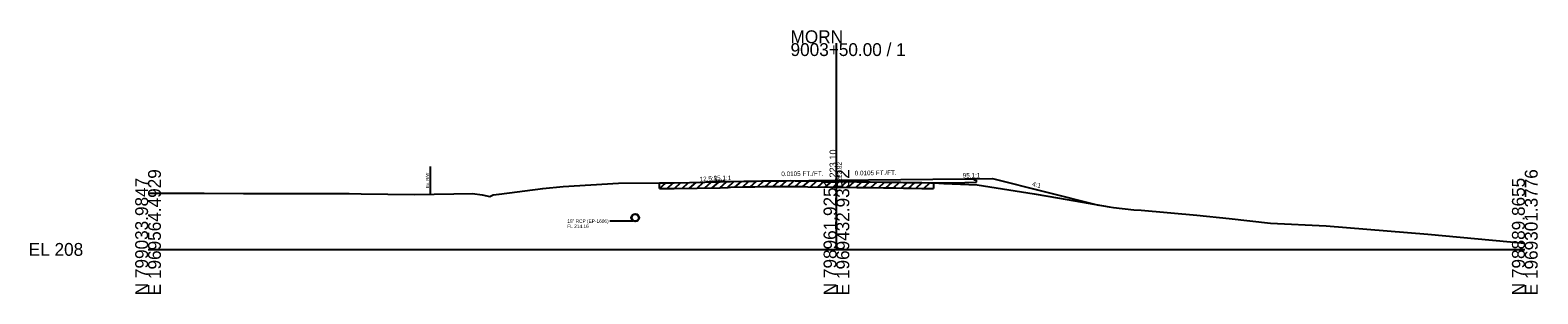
# Model space of a CAD drawing. Extents: x -26 to 2313, y -1511 to 5559.
# Drawn here: x -25.7 to 302.8, y 1490.3 to 1547.8 of the extents above; entities that cross this region are included whole.
import ezdxf

# ---------------------------------------------------------------- set-up
doc = ezdxf.new("R2010")
doc.units = 0
for name, color, linetype in [('RD_GPK_XS_Cell', 7, 'Continuous'), ('RD_XS_Base', 7, 'Continuous'), ('RD_XS_EarthShd', 7, 'Continuous'), ('RD_XS_ExGround', 7, 'Continuous'), ('RD_XS_ExPaveRet', 7, 'Continuous'), ('RD_XS_ExRW', 7, 'Continuous'), ('RD_XS_Misc_Line', 7, 'Continuous'), ('RD_XS_Pave', 7, 'Continuous'), ('RD_XS_PaveOvlay', 7, 'Continuous'), ('RD_XS_PaveShd', 7, 'Continuous'), ('RD_XS_Pipe', 7, 'Continuous'), ('RD_XS_TieSlope', 7, 'Continuous'), ('RD_XS_TX_Elev_EX', 7, 'Continuous'), ('RD_XS_TX_Elev_PR', 7, 'Continuous'), ('RD_XS_TX_Profile', 7, 'Continuous'), ('RD_XS_TX_ShdSlope', 7, 'Continuous'), ('RD_XS_TX_Slope', 7, 'Continuous')]:
    doc.layers.add(name, color=color, linetype=linetype)

msp = doc.modelspace()

# ---------------------------------------------------------------- linework, layer by layer
at = {"layer": 'RD_GPK_XS_Cell'}
for p, q in [((150, 1500), (150, 1544.96)), ((0, 1500), (150, 1500)), ((150, 1500), (300, 1500))]:
    msp.add_line(p, q, dxfattribs=at)
at = {"layer": 'RD_XS_Base'}
for p, q in [((123.72, 1514.68), (123.72, 1514.82)), ((178, 1514.61), (180.5, 1514.64)), ((180, 1515.11), (180, 1515.41)), ((180.5, 1515.12), (180, 1515.11)), ((180.5, 1514.64), (180.5, 1515.12))]:
    msp.add_line(p, q, dxfattribs=at)
at = {"layer": 'RD_XS_EarthShd'}
for p, q in [((123.72, 1514.82), (121.51, 1514.64)), ((180, 1515.41), (184, 1515.45))]:
    msp.add_line(p, q, dxfattribs=at)
at = {"layer": 'RD_XS_ExGround'}
msp.add_lwpolyline([(0, 1512.25), (5.29, 1512.27), (12.21, 1512.25), (20.79, 1512.22), (31.25, 1512.22), (38.81, 1512.2), (43.82, 1512.19), (46.43, 1512.13), (58.04, 1512), (66.62, 1512.1), (70.68, 1512.17), (72.77, 1511.88), (74.46, 1511.55), (75.22, 1511.87), (76.54, 1512.07), (86.05, 1513.31), (90.47, 1513.74), (102.53, 1514.41), (111.43, 1514.53), (114.63, 1514.52), (124.66, 1514.7), (126.44, 1514.78), (126.91, 1514.79), (129.82, 1514.86), (130.15, 1514.86), (130.61, 1514.87), (131.27, 1514.89), (132.24, 1514.9), (133.75, 1514.93), (134.81, 1514.94), (135.64, 1514.96), (136.59, 1514.95), (138.74, 1514.97), (139.14, 1514.97), (140.09, 1514.99), (141, 1514.95), (142.47, 1514.94), (142.83, 1514.94), (143.77, 1514.92), (149.48, 1514.83), (150, 1514.82), (150.46, 1514.81), (154.48, 1514.76), (157.37, 1514.72), (160.29, 1514.68), (162.26, 1514.66), (162.93, 1514.66), (164.58, 1514.62), (165.8, 1514.59), (166.36, 1514.58), (168.58, 1514.55), (170.52, 1514.52), (171.18, 1514.5), (173.43, 1514.39), (180.68, 1514.07), (193.06, 1512.09), (198.58, 1511.17), (209.41, 1509.27), (210.35, 1509.17), (214.79, 1508.66), (216.38, 1508.52), (228.51, 1507.44), (235.61, 1506.74), (244.56, 1505.75), (256.71, 1505.15), (278.85, 1503.32), (300, 1501.36)], dxfattribs=at)
at = {"layer": 'RD_XS_ExPaveRet'}
for p, q in [((111.43, 1513.28), (111.43, 1514.53)), ((111.43, 1513.28), (114.63, 1513.27)), ((114.63, 1513.27), (124.66, 1513.45)), ((124.66, 1513.45), (126.44, 1513.53)), ((126.44, 1513.53), (126.91, 1513.54)), ((126.91, 1513.54), (129.82, 1513.61)), ((129.82, 1513.61), (130.15, 1513.61)), ((130.15, 1513.61), (130.61, 1513.62)), ((130.61, 1513.62), (131.27, 1513.64)), ((131.27, 1513.64), (132.24, 1513.65)), ((132.24, 1513.65), (133.75, 1513.68)), ((133.75, 1513.68), (134.81, 1513.69)), ((134.81, 1513.69), (135.64, 1513.71)), ((135.64, 1513.71), (136.59, 1513.7)), ((136.59, 1513.7), (138.74, 1513.72)), ((138.74, 1513.72), (139.14, 1513.72)), ((139.14, 1513.72), (140.09, 1513.74)), ((140.09, 1513.74), (141, 1513.7)), ((141, 1513.7), (142.47, 1513.69)), ((142.47, 1513.69), (142.83, 1513.69)), ((142.83, 1513.69), (143.77, 1513.67)), ((143.77, 1513.67), (149.48, 1513.58)), ((149.48, 1513.58), (150, 1513.57)), ((150, 1513.57), (150.46, 1513.56)), ((150.46, 1513.56), (154.48, 1513.51)), ((154.48, 1513.51), (157.37, 1513.47)), ((157.37, 1513.47), (160.29, 1513.43)), ((160.29, 1513.43), (162.26, 1513.41)), ((162.26, 1513.41), (162.93, 1513.41)), ((162.93, 1513.41), (164.58, 1513.37)), ((164.58, 1513.37), (165.8, 1513.34)), ((165.8, 1513.34), (166.36, 1513.33)), ((166.36, 1513.33), (168.58, 1513.3)), ((168.58, 1513.3), (170.52, 1513.27)), ((170.52, 1513.27), (171.18, 1513.25)), ((171.18, 1514.5), (171.18, 1513.25))]:
    msp.add_line(p, q, dxfattribs=at)
at = {"layer": 'RD_XS_ExRW'}
msp.add_line((61.46, 1518.04), (61.46, 1512.04), dxfattribs=at)
at = {"layer": 'RD_XS_Misc_Line'}
for p, q in [((114.72, 1513.27), (116.12, 1514.55)), ((116.37, 1513.3), (117.76, 1514.58)), ((118.01, 1513.33), (119.41, 1514.61)), ((119.66, 1513.36), (121.05, 1514.64)), ((121.3, 1513.39), (122.7, 1514.66)), ((122.95, 1513.42), (124.34, 1514.69)), ((124.59, 1513.45), (126.04, 1514.76)), ((126.24, 1513.52), (127.65, 1514.81)), ((127.88, 1513.56), (129.29, 1514.84)), ((129.53, 1513.6), (130.93, 1514.88)), ((131.17, 1513.63), (132.57, 1514.91)), ((132.82, 1513.67), (134.21, 1514.94)), ((134.46, 1513.69), (135.85, 1514.95)), ((136.11, 1513.7), (137.49, 1514.96)), ((137.75, 1513.71), (139.13, 1514.97)), ((139.4, 1513.72), (140.75, 1514.96)), ((141.04, 1513.7), (142.41, 1514.94)), ((142.69, 1513.69), (144.03, 1514.91)), ((144.33, 1513.66), (145.68, 1514.89)), ((145.98, 1513.63), (147.33, 1514.86)), ((147.62, 1513.61), (148.97, 1514.84)), ((149.27, 1513.58), (150.62, 1514.81)), ((150.91, 1513.56), (152.26, 1514.79)), ((152.56, 1513.54), (153.91, 1514.77)), ((154.2, 1513.51), (155.55, 1514.74)), ((155.85, 1513.49), (157.2, 1514.72)), ((157.49, 1513.47), (158.84, 1514.7)), ((159.14, 1513.44), (160.49, 1514.67)), ((160.78, 1513.42), (162.15, 1514.67)), ((162.43, 1513.41), (163.77, 1514.64)), ((164.07, 1513.38), (165.41, 1514.6)), ((165.72, 1513.34), (167.07, 1514.57)), ((167.37, 1513.32), (168.71, 1514.55)), ((111.43, 1513.28), (112.8, 1514.52)), ((113.08, 1513.27), (114.45, 1514.52)), ((169.01, 1513.29), (170.36, 1514.52))]:
    msp.add_line(p, q, dxfattribs=at)
at = {"layer": 'RD_XS_Pave'}
for p, q in [((125.72, 1514.84), (150, 1515.1)), ((150, 1515.1), (178, 1515.39)), ((171.18, 1514.54), (178, 1514.61))]:
    msp.add_line(p, q, dxfattribs=at)
at = {"layer": 'RD_XS_PaveOvlay'}
for p, q in [((123.72, 1514.68), (124.66, 1514.7)), ((124.66, 1514.7), (126.44, 1514.78)), ((126.44, 1514.78), (126.91, 1514.79)), ((126.91, 1514.79), (129.82, 1514.86)), ((129.82, 1514.86), (130.15, 1514.86)), ((130.15, 1514.86), (130.61, 1514.87)), ((130.61, 1514.87), (131.27, 1514.89)), ((131.27, 1514.89), (132.24, 1514.9)), ((132.24, 1514.9), (133.75, 1514.93)), ((133.75, 1514.93), (134.81, 1514.94)), ((134.81, 1514.94), (135.64, 1514.96)), ((135.64, 1514.96), (136.59, 1514.95)), ((136.59, 1514.95), (138.74, 1514.97)), ((138.74, 1514.97), (139.14, 1514.97)), ((139.14, 1514.97), (140.09, 1514.99)), ((140.09, 1514.99), (141, 1514.95)), ((141, 1514.95), (142.47, 1514.94)), ((142.47, 1514.94), (142.83, 1514.94)), ((142.83, 1514.94), (143.77, 1514.92)), ((143.77, 1514.92), (149.48, 1514.83)), ((149.48, 1514.83), (150, 1514.82)), ((150, 1514.82), (150.46, 1514.81)), ((150.46, 1514.81), (154.48, 1514.76)), ((154.48, 1514.76), (157.37, 1514.72)), ((157.37, 1514.72), (160.29, 1514.68)), ((160.29, 1514.68), (162.26, 1514.66)), ((162.26, 1514.66), (162.93, 1514.66)), ((162.93, 1514.66), (164, 1514.63)), ((171.18, 1514.5), (171.18, 1514.54))]:
    msp.add_line(p, q, dxfattribs=at)
at = {"layer": 'RD_XS_PaveShd'}
for p, q in [((125.72, 1514.84), (123.72, 1514.82)), ((178, 1515.39), (180, 1515.41))]:
    msp.add_line(p, q, dxfattribs=at)
at = {"layer": 'RD_XS_Pipe'}
msp.add_line((105.65, 1506.16), (100.65, 1506.16), dxfattribs=at)
for radius in [0.85, 0.75]:
    msp.add_circle((106.15, 1506.91), radius, dxfattribs=at)
at = {"layer": 'RD_XS_TieSlope'}
msp.add_line((184, 1515.45), (207.13, 1509.67), dxfattribs=at)

# ---------------------------------------------------------------- texts
at = {"layer": 'RD_GPK_XS_Cell'}
for s, p in [('MORN', (140, 1544.96)), ('9003+50.00 / 1', (140, 1542.16)), ('EL 208', (-26, 1498.6))]:
    msp.add_text(s, height=2.8, dxfattribs=at).set_placement(p)
for s, p in [('N 799033.9847', (0, 1490)), ('E 1969564.4929', (2.8, 1490)), ('N 798961.9251', (150, 1490)), ('E 1969432.9352', (152.8, 1490)), ('N 798889.8655', (300, 1490)), ('E 1969301.3776', (302.8, 1490))]:
    msp.add_text(s, height=2.8, rotation=90, dxfattribs=at).set_placement(p)
at = {"layer": 'RD_XS_ExRW'}
msp.add_text('Ex. R/W ', height=0.65, rotation=90, dxfattribs=at).set_placement((61.21, 1513.42))
at = {"layer": 'RD_XS_Pipe'}
for s, p in [('18" RCP (EP-1606)', (91.36, 1505.79)), ('FL 214.16', (91.36, 1504.66))]:
    msp.add_text(s, height=0.75, dxfattribs=at).set_placement(p)
at = {"layer": 'RD_XS_TX_Elev_EX'}
msp.add_text('222.82', height=1, rotation=90, dxfattribs=at).set_placement((151.13, 1514.82))
at = {"layer": 'RD_XS_TX_Elev_PR'}
msp.add_text(' 223.10', height=1.5, rotation=90, dxfattribs=at).set_placement((150, 1515.1))
at = {"layer": 'RD_XS_TX_Profile'}
for rotation, p in [(0.6024, (123.24, 1515.07)), (0.6026, (177.52, 1515.64))]:
    msp.add_text('95.1:1', height=1, rotation=rotation, dxfattribs=at).set_placement(p)
at = {"layer": 'RD_XS_TX_ShdSlope'}
msp.add_text('12.5:1', height=1, rotation=4.5723, dxfattribs=at).set_placement((120.23, 1514.79))
at = {"layer": 'RD_XS_TX_Slope'}
for s, rotation, p in [('0.0105 FT./FT.', 0.6024, (137.99, 1515.97)), ('0.0105 FT./FT.', 0.6026, (153.99, 1516.14)), ('4:1', 345.9638, (192.57, 1513.83))]:
    msp.add_text(s, height=1, rotation=rotation, dxfattribs=at).set_placement(p)

doc.saveas('drawing.dxf')
